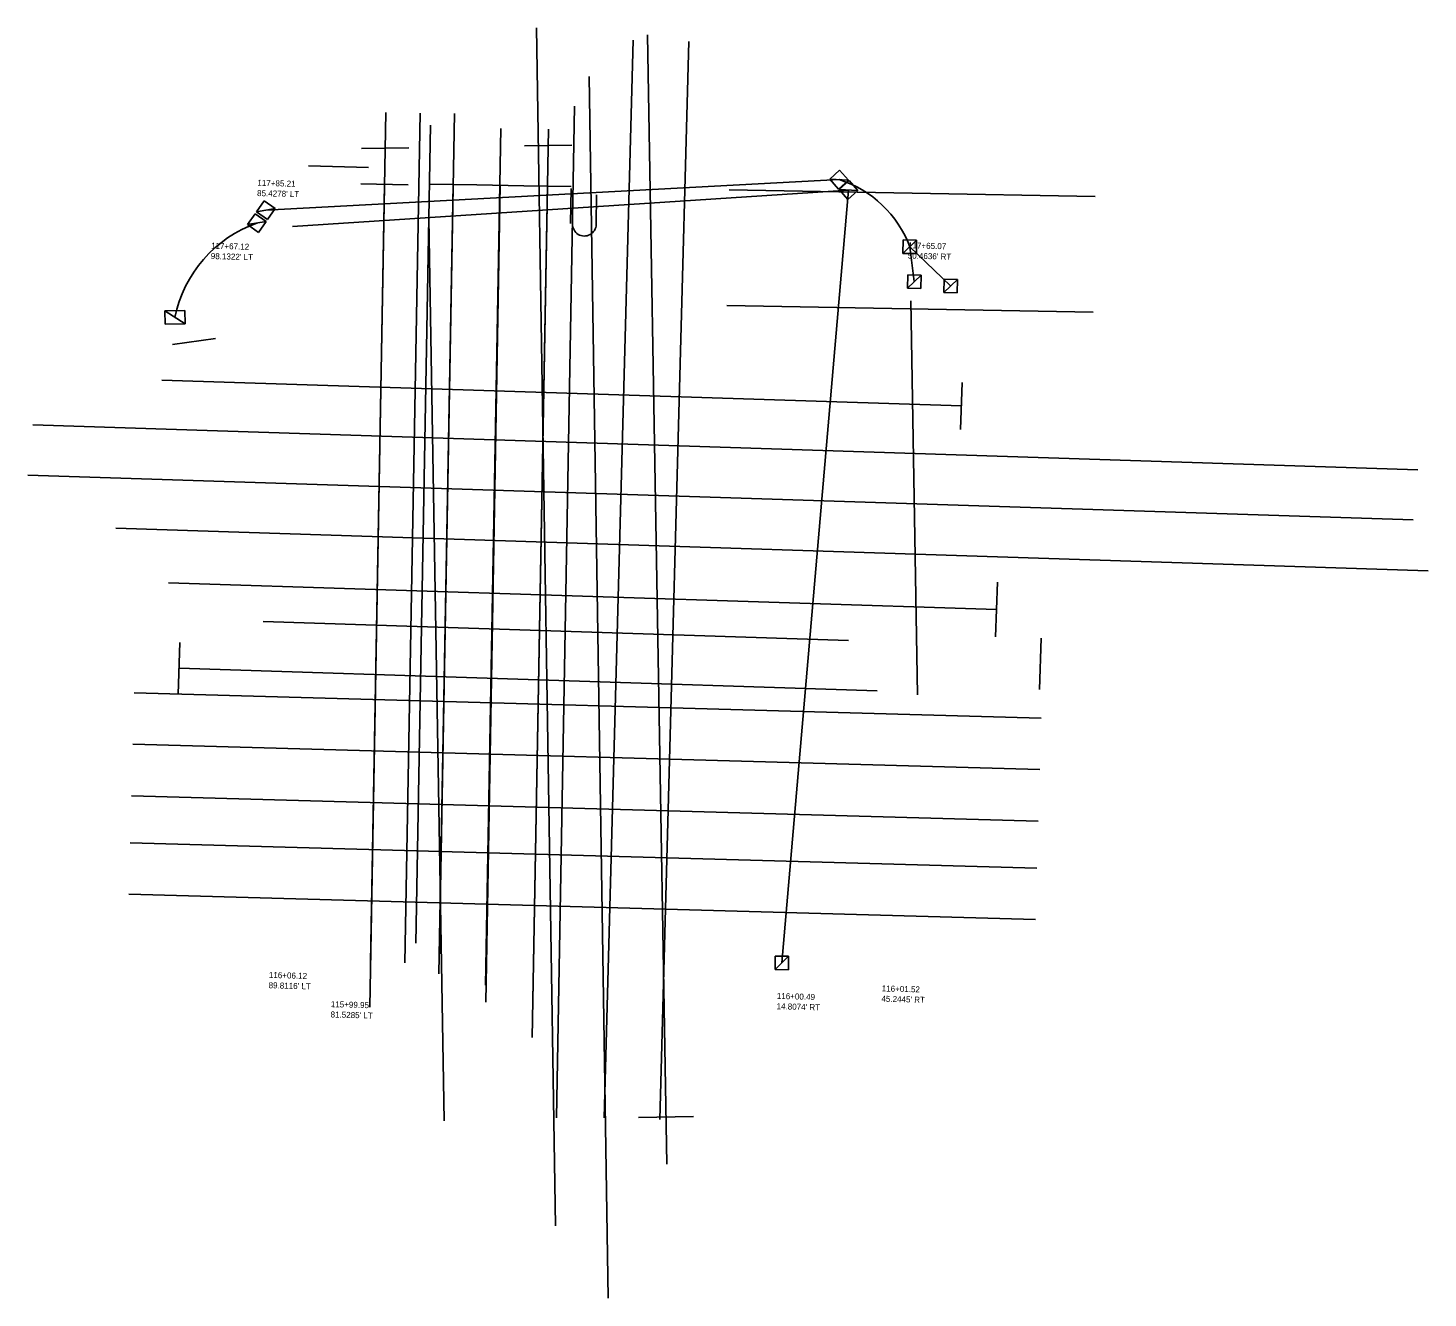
# Model space of a CAD drawing. Extents: x 925680 to 926006, y 853415 to 857998.
# Drawn here: x 925680.1 to 926006.5, y 853415.3 to 853711.4 of the extents above; entities that cross this region are included whole.
import ezdxf

# ---------------------------------------------------------------- set-up
doc = ezdxf.new("R2010")
doc.units = 0
for name, color, linetype in [('ConduitDB', 7, 'Continuous'), ('ConduitOT', 7, 'Continuous'), ('ConstLines', 7, 'Continuous'), ('JunctBoxA', 7, 'Continuous'), ('NonPlottingEle_dp', 7, 'Continuous'), ('PullBox', 7, 'Continuous'), ('PullBox_ep', 7, 'Continuous'), ('ScratchEle2_dp', 7, 'Continuous')]:
    doc.layers.add(name, color=color, linetype=linetype)

msp = doc.modelspace()

# ---------------------------------------------------------------- linework, layer by layer
at = {"layer": 'ConduitDB'}
for p, q in [((925735.59, 853668.95), (925869.2, 853676.09)), ((925871.38, 853673.66), (925741.82, 853665.19)), ((925871.38, 853673.66), (925855.84, 853493.48))]:
    msp.add_line(p, q, dxfattribs=at)
at = {"layer": 'ConduitOT'}
for q in [(925886.7, 853652.32), (925895.19, 853651.29)]:
    msp.add_line((925885.67, 853660.43), q, dxfattribs=at)
for centre, radius, start, end in [((925861.4, 853651.39), 25.9, 20.437, 72.4643), ((925743.34, 853638.12), 29.54, 109.4701, 168.5764)]:
    msp.add_arc(centre, radius, start, end, dxfattribs=at)
at = {"layer": 'ConstLines'}
for p, q in [((925821.17, 853708.61), (925814.44, 853457.33)), ((925834.16, 853708.27), (925827.43, 853456.98)), ((925807.55, 853693.24), (925803.33, 853457.33)), ((925773.58, 853666.98), (925777.16, 853456.64)), ((925885.91, 853647.82), (925887.47, 853555.95))]:
    msp.add_line(p, q, dxfattribs=at)
at = {"layer": 'JunctBoxA'}
for p, q in [((925712.06, 853645.46), (925716.7, 853645.54)), ((925716.7, 853645.54), (925712.06, 853645.46)), ((925712.12, 853642.37), (925712.06, 853645.46)), ((925712.06, 853645.46), (925716.76, 853642.44)), ((925716.7, 853645.54), (925716.76, 853642.44)), ((925716.76, 853642.44), (925716.7, 853645.54)), ((925716.76, 853642.44), (925712.12, 853642.37))]:
    msp.add_line(p, q, dxfattribs=at)
at = {"layer": 'NonPlottingEle_dp'}
for p, q in [((925768.72, 853674.91), (925757.72, 853675.11)), ((925763.22, 853675.01), (925759.78, 853483.16)), ((925773.72, 853675.05), (925784.72, 853674.85)), ((925779.22, 853674.95), (925775.92, 853490.92)), ((925784.72, 853674.85), (925795.72, 853674.66)), ((925790.22, 853674.76), (925786.81, 853484.28)), ((925795.72, 853674.66), (925806.72, 853674.46)), ((925801.22, 853674.56), (925797.82, 853484.67)), ((925806.71, 853674), (925806.56, 853665.83)), ((925812.68, 853672.56), (925812.56, 853665.73)), ((925928.9, 853672.19), (925843.53, 853673.72)), ((925928.42, 853645.19), (925843.05, 853646.72)), ((925897.69, 853623.31), (925711.32, 853629.35)), ((925897.51, 853617.8), (925897.87, 853628.82)), ((926004.06, 853608.44), (925681.22, 853618.9)), ((926002.97, 853596.74), (925680.13, 853607.2)), ((926006.46, 853584.89), (925700.62, 853594.79)), ((925905.88, 853575.86), (925712.86, 853582.11)), ((925905.67, 853569.52), (925906.08, 853582.2)), ((925871.38, 853568.63), (925734.93, 853573.05)), ((925715.14, 853556.15), (925715.53, 853568.2)), ((925916.3, 853569.19), (925915.91, 853557.2)), ((925715.34, 853562.18), (925878.03, 853556.91)), ((925704.91, 853556.44), (925916.29, 853550.54)), ((925704.58, 853544.44), (925915.95, 853538.55)), ((925704.24, 853532.45), (925915.62, 853526.55)), ((925703.94, 853521.45), (925915.31, 853515.56)), ((925703.6, 853509.46), (925914.98, 853503.56))]:
    msp.add_line(p, q, dxfattribs=at)
msp.add_arc((925809.81, 853665.68), 2.75, 178.9741, 358.9741, dxfattribs=at)
at = {"layer": 'PullBox'}
for p, q in [((925867, 853676.21), (925869.32, 853678.29)), ((925869.32, 853678.29), (925871.41, 853675.97)), ((925869.08, 853673.88), (925867, 853676.21)), ((925867, 853676.21), (925871.41, 853675.97)), ((925871.41, 853675.97), (925869.08, 853673.88)), ((925869.17, 853673.78), (925871.5, 853675.86)), ((925871.5, 853675.86), (925873.59, 853673.54)), ((925733.41, 853668.57), (925735.21, 853671.12)), ((925735.21, 853671.12), (925737.76, 853669.33)), ((925871.26, 853671.45), (925869.17, 853673.78)), ((925869.17, 853673.78), (925873.59, 853673.54)), ((925873.59, 853673.54), (925871.26, 853671.45)), ((925731.32, 853665.59), (925733.11, 853668.15)), ((925733.11, 853668.15), (925735.67, 853666.35)), ((925733.41, 853668.57), (925737.76, 853669.33)), ((925735.97, 853666.77), (925733.41, 853668.57)), ((925737.76, 853669.33), (925735.97, 853666.77)), ((925731.32, 853665.59), (925735.67, 853666.35)), ((925733.87, 853663.79), (925731.32, 853665.59)), ((925735.67, 853666.35), (925733.87, 853663.79)), ((925884.08, 853658.9), (925884.13, 853662.02)), ((925884.08, 853658.9), (925887.26, 853661.97)), ((925884.13, 853662.02), (925887.26, 853661.97)), ((925887.26, 853661.97), (925887.2, 853658.84)), ((925887.2, 853658.84), (925884.08, 853658.9)), ((925854.25, 853491.94), (925854.3, 853495.07)), ((925854.25, 853491.94), (925857.43, 853495.01)), ((925854.3, 853495.07), (925857.43, 853495.01)), ((925857.43, 853495.01), (925857.37, 853491.89)), ((925857.37, 853491.89), (925854.25, 853491.94))]:
    msp.add_line(p, q, dxfattribs=at)
at = {"layer": 'PullBox_ep'}
for p, q in [((925885.11, 853650.82), (925885.2, 853653.91)), ((925885.11, 853650.82), (925888.29, 853653.82)), ((925885.2, 853653.91), (925888.29, 853653.82)), ((925888.29, 853653.82), (925888.21, 853650.73)), ((925893.6, 853649.79), (925893.68, 853652.88)), ((925893.6, 853649.79), (925896.78, 853652.79)), ((925893.68, 853652.88), (925896.78, 853652.79)), ((925896.78, 853652.79), (925896.69, 853649.7)), ((925888.21, 853650.73), (925885.11, 853650.82)), ((925896.69, 853649.7), (925893.6, 853649.79))]:
    msp.add_line(p, q, dxfattribs=at)
at = {"layer": 'ScratchEle2_dp'}
for p, q in [((925798.69, 853711.44), (925803.07, 853432.2)), ((925829.04, 853446.57), (925824.52, 853709.82)), ((925815.37, 853415.34), (925810.9, 853700.12)), ((925763.52, 853691.77), (925759.97, 853493.66)), ((925771.52, 853691.62), (925767.97, 853493.51)), ((925779.52, 853691.48), (925775.97, 853493.37)), ((925773.97, 853688.76), (925770.55, 853498.1)), ((925790.32, 853688.01), (925786.74, 853488.27)), ((925801.46, 853687.88), (925797.66, 853476.1)), ((925806.89, 853684.14), (925795.88, 853683.95)), ((925757.87, 853683.31), (925768.87, 853683.49)), ((925745.55, 853679.27), (925759.51, 853678.94)), ((925713.85, 853637.68), (925723.82, 853639.03)), ((925835.28, 853457.68), (925822.42, 853457.46))]:
    msp.add_line(p, q, dxfattribs=at)

# ---------------------------------------------------------------- texts
at = {"layer": 'NonPlottingEle_dp'}
for s, p in [('117+85.21', (925733.58, 853674.66)), ("85.4278' LT", (925733.51, 853672.26)), ('117+67.12', (925722.78, 853659.98)), ('117+65.07', (925885.25, 853660.09)), ("98.1322' LT", (925722.72, 853657.58)), ("50.4636' RT", (925885.18, 853657.69)), ("89.8116' LT", (925736.2, 853487.57)), ('116+06.12', (925736.27, 853489.97)), ('116+00.49', (925854.66, 853485.07)), ("45.2445' RT", (925879.04, 853484.43)), ('116+01.52', (925879.11, 853486.83)), ("81.5285' LT", (925750.64, 853480.76)), ('115+99.95', (925750.7, 853483.16)), ("14.8074' RT", (925854.6, 853482.68))]:
    msp.add_text(s, height=1.4, rotation=358.3939, dxfattribs=at).set_placement(p)

doc.saveas('drawing.dxf')
